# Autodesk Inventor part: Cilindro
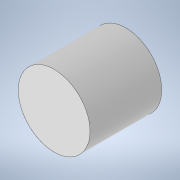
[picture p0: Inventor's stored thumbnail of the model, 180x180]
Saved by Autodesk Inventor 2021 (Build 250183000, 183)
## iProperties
Created: 2021-02
Part Number: Cilindro
Material: Genérico
Document SubType Name: Modeling
Designer: ATOUZA
Density: 1 g/cm^3
Appearance: Valor por defecto
Author: ATOUZA
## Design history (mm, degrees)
sketch "Boceto1"
  geometry: C1 r 17.5 at (0, 0); 1 further point
  constraints: 1 centre point, 1 coincident
  dimensions: "d0" = 35 diameter of C1
extrude "Extrusión1" new body sketch "Boceto1" distance "d1" = 35; taper "d2" = 0 deg
node "Sólido1"
